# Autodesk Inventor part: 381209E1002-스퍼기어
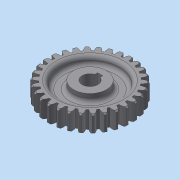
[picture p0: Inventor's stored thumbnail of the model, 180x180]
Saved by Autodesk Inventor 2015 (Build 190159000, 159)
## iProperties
Created: 2018-12
Part Number: 381209E1002-스퍼기어
Material: 일반
Document SubType Name: Modeling
Designer: iamsam
Density: 1 g/cm^3
Appearance: 기본값
Author: iamsam
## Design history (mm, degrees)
sketch "스케치1" dims "d2" = 4.5
  geometry: L1 (0, 0)-(0, 39.499); L2 (-1.57, 18.913)-(-1.57, 38.511); L3 (-0.57, 21.969)-(-0.57, 37.072); L4 (-2.07, 21.789)-(-2.07, 36.892); C1 r 30 at (0, 0); A1 r 9.292 centre (7.208, 26.911) between (-0.57, 31.995) and (-2.07, 27.422); A2 r 9.292 centre (-7.208, 26.911) between (2.07, 27.422) and (0.57, 31.995); A3 r 32 centre (0, 0) between (0.57, 31.995) and (-0.57, 31.995); A4 r 27.5 centre (0, 0) between (2.07, 27.422) and (-2.07, 27.422); 2 further points
  constraints: 8 end point, 8 point on circle, 5 centre point, 4 vertical, 3 coincident, 3 symmetric about line, 2 point on line, 9 other
  dimensions: "d0" = 60 diameter of C1; "d1" = 2 dimension on C1; "d3" = 1.57 distance between parallel lines of L2 L1; "d4" = 1 distance between parallel lines of L2 L3; "d5" = 0.5 distance between parallel lines of L4 L2
extrude "돌출1" new body sketch "스케치1" distance "d6" = 13; taper "d7" = 0 deg
chamfer "모따기1" distance "d8" = 1; stored, may be unused: second distance "d9" = 2, angle "d10" = 45 deg
sketch "스케치3"
  geometry: L1 (-31, 0)-(-32, 1) reference; L2 (-32, 1)-(-32, 12) reference; L3 (-32, 12)-(-31, 13) reference; L4 (-31, 13)-(31, 13) reference; L5 (31, 13)-(32, 12) reference; L6 (32, 12)-(32, 1) reference; L7 (32, 1)-(31, 0) reference; L8 (31, 0)-(-31, 0) reference; L9 (0, 0)-(0, 13); L10 (12.5, 7)-(22.5, 7); L11 (22.5, 7)-(22.5, 13); L12 (22.5, 13)-(12.5, 13); L13 (12.5, 13)-(12.5, 7); L14 (12.5, 7)-(22.5, 13); L15 (22.5, 7)-(12.5, 13); 1 further point
  constraints: 14 end point, 3 midpoint, 2 parallel, 1 horizontal, 1 perpendicular, 1 point on line, 1 vertical
  dimensions: "d15" = 45 diameter of L11 L9; "d16" = 25 diameter of L13 L9; "d17" = 6 distance of L10.end L11.end
revolve "회전1" sketch "스케치3" stored, may be unused: angle "d18" = 90 deg
fillet "모깎기1" dims "d19" = 3
sketch "스케치4"
  geometry: L1 (2, 5.657)-(2, 7.8); L2 (2, 7.8)-(-2, 7.8); L3 (-2, 7.8)-(-2, 5.657); A1 r 6 centre (0, 0) between (-2, 5.657) and (2, 5.657); 1 further point
  constraints: 6 end point, 2 point on circle, 1 centre point, 1 coincident, 1 horizontal, 1 horizontal alignment, 1 parallel, 1 vertical
  dimensions: "d20" = 6 radius of A1; "d21" = 13.8 dimension on A1 L2; "d22" = 4 distance of L1.end L2.end
extrude "돌출2" cut sketch "스케치4" stored distance "d23" = 13; taper "d24" = 0 deg
chamfer "모따기2" distance "d25" = 1; stored, may be unused: second distance "d26" = 2, angle "d27" = 45 deg
node "솔리드1"
pattern_circular "원형 패턴1" dims angle "d12" = 360 deg
node "절단 모서리 투영1"
